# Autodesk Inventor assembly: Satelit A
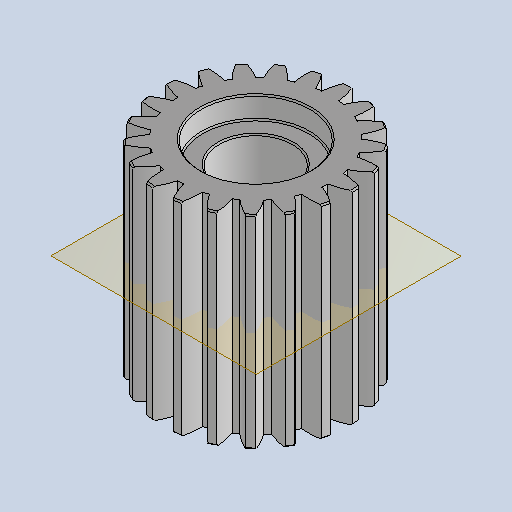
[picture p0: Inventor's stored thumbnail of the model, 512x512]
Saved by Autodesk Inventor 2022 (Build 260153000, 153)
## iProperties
Created: 2025-05
Part Number: Satelit A
Document SubType Name: Assembly
Designer: jbart
Mass: 1423.69 g
Surface Area: 1668.6 cm^2
Volume: 1423.69 cm^3
Density: 1 g/cm^3
Author: jbart
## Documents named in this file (2)
- C:\Users\jbart\OneDrive\Dokumenty\Inventor\Převodovka navijáku\Satelit A.iam
- C:\Users\jbart\OneDrive\Dokumenty\Inventor\Převodovka navijáku\Satelit A\Design Accelerator\Čelní ozubená kola1.iam
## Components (1 placed, 1 different names)
1. Čelní ozubená kola:1 [sub-assembly]
